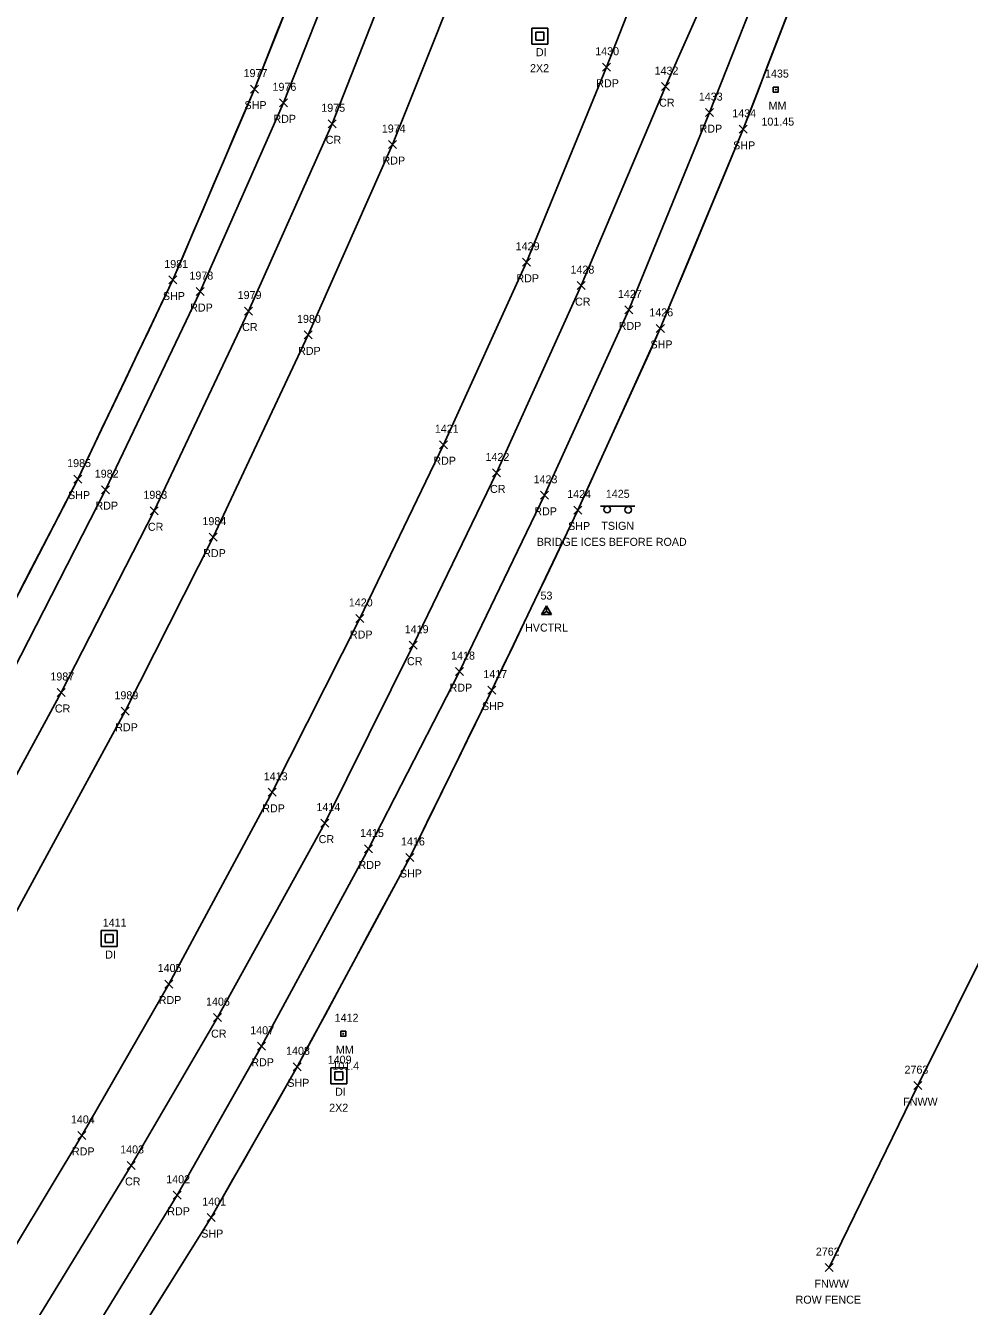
# Model space of a CAD drawing. Extents: x 1472022 to 1479249, y 777216 to 786527.
# Drawn here: x 1473340.4 to 1473576.1, y 778431.9 to 778752 of the extents above; entities that cross this region are included whole.
import ezdxf

# ---------------------------------------------------------------- set-up
doc = ezdxf.new("R2010")
doc.units = 0
for name, color, linetype in [('C_A', 7, 'Continuous'), ('C_I', 7, 'Continuous'), ('CPSM', 7, 'Continuous'), ('D_A', 7, 'Continuous'), ('D_C', 7, 'Continuous'), ('D_I', 7, 'Continuous'), ('DS', 7, 'Continuous'), ('L_A', 7, 'Continuous'), ('L_C', 7, 'Continuous'), ('L_I', 7, 'Continuous'), ('L_TIC', 7, 'Continuous'), ('LFNC', 7, 'Continuous'), ('LSOGP', 7, 'Continuous'), ('P_A', 7, 'Continuous'), ('P_I', 7, 'Continuous'), ('P_TIC', 7, 'Continuous'), ('PET', 7, 'Continuous'), ('PRC', 7, 'Continuous'), ('PSP', 7, 'Continuous'), ('S_A', 7, 'Continuous'), ('S_C', 7, 'Continuous'), ('S_I', 7, 'Continuous'), ('SRM', 7, 'Continuous'), ('SSGN', 7, 'Continuous')]:
    doc.layers.add(name, color=color, linetype=linetype)

msp = doc.modelspace()

# ---------------------------------------------------------------- linework, layer by layer
at = {"layer": 'CPSM'}
for p, q in [((1473469.19, 778604.84), (1473470.44, 778607.01)), ((1473469.19, 778604.84), (1473470.44, 778605.56)), ((1473469.19, 778604.84), (1473471.69, 778604.84)), ((1473471.69, 778604.84), (1473470.44, 778607.01)), ((1473470.44, 778605.56), (1473470.44, 778607.01)), ((1473470.44, 778605.56), (1473470.44, 778605.56)), ((1473470.44, 778605.56), (1473471.69, 778604.84))]:
    msp.add_line(p, q, dxfattribs=at)
at = {"layer": 'DS'}
for p, q in [((1473466.78, 778751.36), (1473470.78, 778751.36)), ((1473466.78, 778747.36), (1473466.78, 778751.36)), ((1473467.78, 778748.36), (1473467.78, 778750.36)), ((1473467.78, 778750.36), (1473469.78, 778750.36)), ((1473469.78, 778748.36), (1473467.78, 778748.36)), ((1473468.79, 778749.36), (1473468.79, 778749.36)), ((1473468.79, 778749.36), (1473468.79, 778749.36)), ((1473469.78, 778750.36), (1473469.78, 778748.36)), ((1473470.78, 778751.36), (1473470.78, 778747.36)), ((1473470.78, 778747.36), (1473466.78, 778747.36)), ((1473359.21, 778525.83), (1473363.21, 778525.83)), ((1473359.21, 778521.83), (1473359.21, 778525.83)), ((1473360.21, 778522.83), (1473360.21, 778524.83)), ((1473360.21, 778524.83), (1473362.21, 778524.83)), ((1473362.21, 778524.83), (1473362.21, 778522.83)), ((1473363.21, 778525.83), (1473363.21, 778521.83)), ((1473363.21, 778521.83), (1473359.21, 778521.83)), ((1473362.21, 778522.83), (1473360.21, 778522.83)), ((1473361.21, 778523.84), (1473361.21, 778523.84)), ((1473361.21, 778523.84), (1473361.21, 778523.84)), ((1473416.62, 778491.57), (1473420.62, 778491.57)), ((1473416.62, 778487.57), (1473416.62, 778491.57)), ((1473417.62, 778488.57), (1473417.62, 778490.57)), ((1473417.62, 778490.57), (1473419.62, 778490.57)), ((1473418.62, 778489.57), (1473418.62, 778489.57)), ((1473418.62, 778489.57), (1473418.62, 778489.57)), ((1473419.62, 778490.57), (1473419.62, 778488.57)), ((1473420.62, 778491.57), (1473420.62, 778487.57)), ((1473420.62, 778487.57), (1473416.62, 778487.57)), ((1473419.62, 778488.57), (1473417.62, 778488.57))]:
    msp.add_line(p, q, dxfattribs=at)
at = {"layer": 'L_TIC'}
for points in [[(1473562.21, 778486.09), (1473564.21, 778488.09)], [(1473564.21, 778486.09), (1473562.21, 778488.09)], [(1473540.06, 778440.61), (1473542.06, 778442.61)], [(1473542.06, 778440.61), (1473540.06, 778442.61)]]:
    msp.add_lwpolyline(points, dxfattribs=at)
at = {"layer": 'LFNC'}
msp.add_lwpolyline([(1473541.06, 778441.61), (1473563.21, 778487.09), (1473582.35, 778525.63), (1473607.06, 778564.79), (1473620.48, 778587.36), (1473636.9, 778615.99), (1473667.35, 778667.85), (1473688.74, 778703.58), (1473697.71, 778720.36), (1473722.81, 778762.74), (1473752.79, 778816.55), (1473766.47, 778860.32), (1473785.95, 778933.66), (1473793.25, 778964.66), (1473799.84, 778991.84), (1473803.88, 779010.25), (1473815.37, 779068.14), (1473825.67, 779115.79)], dxfattribs=at)
at = {"layer": 'LSOGP'}
for points in [[(1473405.86, 778757.09), (1473403.08, 778750.1), (1473400.3, 778743.12), (1473397.52, 778736.13), (1473394.97, 778730.17), (1473392.42, 778724.21), (1473389.87, 778718.24), (1473387.33, 778712.28), (1473384.78, 778706.32), (1473382.23, 778700.36), (1473379.69, 778694.39), (1473377.14, 778688.43), (1473374.18, 778682.21), (1473371.22, 778675.99), (1473368.26, 778669.77), (1473365.29, 778663.55), (1473362.33, 778657.33), (1473359.37, 778651.11), (1473356.41, 778644.89), (1473353.45, 778638.67), (1473350.53, 778633.06), (1473347.61, 778627.44), (1473344.69, 778621.83), (1473341.77, 778616.21), (1473338.85, 778610.6)], [(1473370.08, 778427.53), (1473373.41, 778432.85), (1473376.73, 778438.16), (1473380.06, 778443.48), (1473383.38, 778448.8), (1473386.71, 778454.12), (1473389.39, 778458.83), (1473392.08, 778463.54), (1473394.77, 778468.25), (1473397.46, 778472.96), (1473400.15, 778477.67), (1473402.84, 778482.38), (1473405.52, 778487.09), (1473408.21, 778491.8), (1473411.73, 778498.34), (1473415.24, 778504.88), (1473418.75, 778511.42), (1473422.27, 778517.96), (1473425.78, 778524.5), (1473429.3, 778531.03), (1473432.81, 778537.57), (1473436.32, 778544.11), (1473438.89, 778549.34), (1473441.45, 778554.57), (1473444.01, 778559.8), (1473446.58, 778565.02), (1473449.14, 778570.25), (1473451.7, 778575.48), (1473454.26, 778580.71), (1473456.83, 778585.94), (1473459.52, 778591.56), (1473462.21, 778597.19), (1473464.9, 778602.81), (1473467.59, 778608.44), (1473470.28, 778614.06), (1473472.97, 778619.69), (1473475.66, 778625.31), (1473478.34, 778630.94), (1473480.92, 778636.61), (1473483.49, 778642.29), (1473486.06, 778647.96), (1473488.63, 778653.63), (1473491.2, 778659.31), (1473493.77, 778664.98), (1473496.34, 778670.66), (1473498.91, 778676.33), (1473501.49, 778682.55), (1473504.08, 778688.77), (1473506.66, 778694.99), (1473509.24, 778701.21), (1473511.82, 778707.43), (1473514.41, 778713.64), (1473516.99, 778719.86), (1473519.57, 778726.08), (1473521.56, 778731.24), (1473523.56, 778736.4), (1473525.55, 778741.56), (1473527.54, 778746.72), (1473529.53, 778751.88), (1473531.53, 778757.04)]]:
    msp.add_lwpolyline(points, dxfattribs=at)
at = {"layer": 'P_TIC'}
for points in [[(1473484.43, 778740.59), (1473486.43, 778742.59)], [(1473486.43, 778740.59), (1473484.43, 778742.59)], [(1473396.52, 778735.13), (1473398.52, 778737.13)], [(1473398.52, 778735.13), (1473396.52, 778737.13)], [(1473499.17, 778735.74), (1473501.17, 778737.74)], [(1473501.17, 778735.74), (1473499.17, 778737.74)], [(1473403.79, 778731.7), (1473405.79, 778733.7)], [(1473405.79, 778731.7), (1473403.79, 778733.7)], [(1473510.23, 778729.25), (1473512.23, 778731.25)], [(1473512.23, 778729.25), (1473510.23, 778731.25)], [(1473415.92, 778726.46), (1473417.92, 778728.46)], [(1473417.92, 778726.46), (1473415.92, 778728.46)], [(1473518.57, 778725.08), (1473520.57, 778727.08)], [(1473520.57, 778725.08), (1473518.57, 778727.08)], [(1473431.04, 778721.28), (1473433.04, 778723.28)], [(1473433.04, 778721.28), (1473431.04, 778723.28)], [(1473464.48, 778691.86), (1473466.48, 778693.86)], [(1473466.48, 778691.86), (1473464.48, 778693.86)], [(1473376.14, 778687.43), (1473378.14, 778689.43)], [(1473378.14, 778687.43), (1473376.14, 778689.43)], [(1473478.17, 778686.02), (1473480.17, 778688.02)], [(1473480.17, 778686.02), (1473478.17, 778688.02)], [(1473382.99, 778684.53), (1473384.99, 778686.53)], [(1473384.99, 778684.53), (1473382.99, 778686.53)], [(1473395.04, 778679.67), (1473397.04, 778681.67)], [(1473397.04, 778679.67), (1473395.04, 778681.67)], [(1473490.01, 778679.96), (1473492.01, 778681.96)], [(1473492.01, 778679.96), (1473490.01, 778681.96)], [(1473409.95, 778673.71), (1473411.95, 778675.71)], [(1473411.95, 778673.71), (1473409.95, 778675.71)], [(1473497.91, 778675.33), (1473499.91, 778677.33)], [(1473499.91, 778675.33), (1473497.91, 778677.33)], [(1473443.72, 778646.26), (1473445.72, 778648.26)], [(1473445.72, 778646.26), (1473443.72, 778648.26)], [(1473352.45, 778637.67), (1473354.45, 778639.67)], [(1473354.45, 778637.67), (1473352.45, 778639.67)], [(1473456.95, 778639.21), (1473458.95, 778641.21)], [(1473458.95, 778639.21), (1473456.95, 778641.21)], [(1473359.34, 778635.02), (1473361.34, 778637.02)], [(1473361.34, 778635.02), (1473359.34, 778637.02)], [(1473468.94, 778633.62), (1473470.94, 778635.62)], [(1473470.94, 778633.62), (1473468.94, 778635.62)], [(1473371.49, 778629.75), (1473373.49, 778631.75)], [(1473373.49, 778629.75), (1473371.49, 778631.75)], [(1473477.34, 778629.94), (1473479.34, 778631.94)], [(1473479.34, 778629.94), (1473477.34, 778631.94)], [(1473386.24, 778623.16), (1473388.24, 778625.16)], [(1473388.24, 778623.16), (1473386.24, 778625.16)], [(1473422.89, 778602.83), (1473424.89, 778604.83)], [(1473424.89, 778602.83), (1473422.89, 778604.83)], [(1473436.21, 778596.16), (1473438.21, 778598.16)], [(1473438.21, 778596.16), (1473436.21, 778598.16)], [(1473447.78, 778589.55), (1473449.78, 778591.55)], [(1473449.78, 778589.55), (1473447.78, 778591.55)], [(1473348.26, 778584.34), (1473350.26, 778586.34)], [(1473350.26, 778584.34), (1473348.26, 778586.34)], [(1473455.83, 778584.94), (1473457.83, 778586.94)], [(1473457.83, 778584.94), (1473455.83, 778586.94)], [(1473364.27, 778579.65), (1473366.27, 778581.65)], [(1473366.27, 778579.65), (1473364.27, 778581.65)], [(1473400.99, 778559.39), (1473402.99, 778561.39)], [(1473402.99, 778559.39), (1473400.99, 778561.39)], [(1473414.13, 778551.7), (1473416.13, 778553.7)], [(1473416.13, 778551.7), (1473414.13, 778553.7)], [(1473425.04, 778545.24), (1473427.04, 778547.24)], [(1473427.04, 778545.24), (1473425.04, 778547.24)], [(1473435.32, 778543.11), (1473437.32, 778545.11)], [(1473437.32, 778543.11), (1473435.32, 778545.11)], [(1473375.14, 778511.49), (1473377.14, 778513.49)], [(1473377.14, 778511.49), (1473375.14, 778513.49)], [(1473387.27, 778503.09), (1473389.27, 778505.09)], [(1473389.27, 778503.09), (1473387.27, 778505.09)], [(1473398.26, 778495.93), (1473400.26, 778497.93)], [(1473400.26, 778495.93), (1473398.26, 778497.93)], [(1473407.21, 778490.8), (1473409.21, 778492.8)], [(1473409.21, 778490.8), (1473407.21, 778492.8)], [(1473353.46, 778473.65), (1473355.46, 778475.65)], [(1473355.46, 778473.65), (1473353.46, 778475.65)], [(1473365.77, 778466.15), (1473367.77, 778468.15)], [(1473367.77, 778466.15), (1473365.77, 778468.15)], [(1473377.27, 778458.7), (1473379.27, 778460.7)], [(1473379.27, 778458.7), (1473377.27, 778460.7)], [(1473385.71, 778453.12), (1473387.71, 778455.12)], [(1473387.71, 778453.12), (1473385.71, 778455.12)]]:
    msp.add_lwpolyline(points, dxfattribs=at)
at = {"layer": 'PET'}
for points in [[(1473559.55, 779345.54), (1473562.13, 779344.85), (1473559.08, 779325.48), (1473547.78, 779268.19), (1473538.56, 779219.47), (1473529.75, 779172.07), (1473520.23, 779121.16), (1473510.25, 779071.91), (1473501.42, 779032.79), (1473487.97, 778980.7), (1473476.59, 778937.83), (1473460.83, 778885.95), (1473443.7, 778834.83), (1473427.04, 778789.1), (1473404.79, 778732.7), (1473383.99, 778685.53), (1473360.34, 778636.02), (1473337.25, 778590.82), (1473309.69, 778539.48), (1473284.14, 778496.13), (1473255.52, 778449.63), (1473221.14, 778399.57)], [(1473562.13, 779344.85), (1473573.79, 779342.6), (1473588.74, 779339.91), (1473585.78, 779323.26), (1473585.84, 779321.4), (1473576.73, 779269.38), (1473567.96, 779217.59), (1473558.64, 779166.28), (1473549.3, 779116.91), (1473539.05, 779065.97), (1473530.44, 779026.51), (1473516.8, 778971.79), (1473504.7, 778929.77), (1473489.22, 778877.79), (1473471.58, 778825.33), (1473455.05, 778780.13), (1473432.04, 778722.28), (1473410.95, 778674.71), (1473387.24, 778624.16), (1473365.27, 778580.65), (1473335.21, 778525.25), (1473309.35, 778481.56), (1473280.39, 778434.36), (1473245.89, 778383.45)], [(1473301.45, 778389.87), (1473329.64, 778433.49), (1473354.46, 778474.65), (1473376.14, 778512.49), (1473401.99, 778560.39), (1473423.89, 778603.83), (1473444.72, 778647.26), (1473465.48, 778692.86), (1473485.43, 778741.59), (1473500.45, 778779.97), (1473517.46, 778826.05), (1473530.33, 778868.32), (1473543.81, 778911.93), (1473556.66, 778958.65), (1473567.98, 779002.48), (1473580.14, 779054.81), (1473589.43, 779101.31), (1473598.46, 779148.03), (1473608.13, 779200.81), (1473618, 779253.28), (1473624.21, 779286.68), (1473629.11, 779313.19), (1473632.64, 779331.64)], [(1473351.95, 778416.72), (1473378.27, 778459.7), (1473399.26, 778496.93), (1473426.04, 778546.24), (1473448.78, 778590.55), (1473469.94, 778634.62), (1473491.01, 778680.96), (1473511.23, 778730.25), (1473526.94, 778770.17), (1473542.8, 778815.57), (1473557.74, 778859.7), (1473571.44, 778904.64), (1473584.34, 778950.97), (1473595.35, 778994.87), (1473607.13, 779045.13), (1473617.39, 779095.53), (1473626.97, 779145.31), (1473636.44, 779196.8), (1473646.17, 779249.15), (1473652.07, 779281.25), (1473656.8, 779307.9), (1473660.32, 779326.69), (1473648.23, 779328.95), (1473632.64, 779331.64)]]:
    msp.add_lwpolyline(points, dxfattribs=at)
at = {"layer": 'PRC'}
for points in [[(1473573.79, 779342.6), (1473570.41, 779324.08), (1473560.67, 779266.03), (1473551.92, 779218.05), (1473542.92, 779169.19), (1473533.33, 779119.74), (1473523.22, 779068.95), (1473514.33, 779029.92), (1473501.09, 778976.92), (1473489.49, 778934.86), (1473473.76, 778882.81), (1473456.11, 778830.27), (1473439.73, 778785.61), (1473416.92, 778727.46), (1473396.04, 778680.67), (1473372.49, 778630.75), (1473349.26, 778585.34), (1473321.1, 778533.63), (1473295.37, 778489.48), (1473266.55, 778442.63), (1473232.46, 778392.44)], [(1473340.44, 778424.05), (1473366.77, 778467.15), (1473388.27, 778504.09), (1473415.13, 778552.7), (1473437.21, 778597.16), (1473457.95, 778640.21), (1473479.17, 778687.02), (1473500.17, 778736.74), (1473516.94, 778774.63), (1473530.88, 778819.91), (1473544.58, 778863.11), (1473558.69, 778908.68), (1473571.41, 778953.91), (1473582.65, 778997.42), (1473594.11, 779047.2), (1473604.41, 779097.99), (1473613.95, 779144.11), (1473624.22, 779197.73), (1473633.15, 779249.53), (1473640.4, 779286.65), (1473645.03, 779310.08), (1473648.23, 779328.95)]]:
    msp.add_lwpolyline(points, dxfattribs=at)
at = {"layer": 'PSP'}
for points in [[(1473559.55, 779345.54), (1473556.55, 779328.39), (1473555.66, 779326.52), (1473543.65, 779268.7), (1473533.24, 779220.88), (1473523.59, 779172.64), (1473513.3, 779122.79), (1473502.95, 779073.62), (1473494.24, 779034.96), (1473482.21, 778985.43), (1473469.56, 778939.68), (1473453.46, 778887.37), (1473437.09, 778838.65), (1473419.76, 778792.02), (1473397.52, 778736.13), (1473377.14, 778688.43), (1473353.45, 778638.67), (1473330.09, 778593.76), (1473303, 778543.94), (1473277.25, 778499.77), (1473248.4, 778453.47), (1473214.72, 778403.13)], [(1473360.11, 778411.57), (1473386.71, 778454.12), (1473408.21, 778491.8), (1473436.32, 778544.11), (1473456.83, 778585.94), (1473478.34, 778630.94), (1473498.91, 778676.33), (1473519.57, 778726.08), (1473535.51, 778767.36), (1473551.79, 778812.35), (1473566.71, 778857.26), (1473580.68, 778902.68), (1473593.4, 778949.04), (1473604.43, 778993.44), (1473615.75, 779042.5), (1473626.64, 779093.98), (1473636.29, 779143.66), (1473644.06, 779195.83), (1473651.7, 779249.18), (1473655.52, 779279.56), (1473658.83, 779307.84), (1473662.07, 779326.37), (1473660.32, 779326.69)]]:
    msp.add_lwpolyline(points, dxfattribs=at)
at = {"layer": 'SRM'}
for points in [[(1473527.13, 778736.64), (1473528.38, 778736.64), (1473528.38, 778735.39), (1473527.13, 778735.39)], [(1473419.07, 778500.68), (1473420.32, 778500.68), (1473420.32, 778499.43), (1473419.07, 778499.43)]]:
    msp.add_lwpolyline(points, close=True, dxfattribs=at)
for centre in [(1473527.75, 778736.01), (1473419.69, 778500.05)]:
    msp.add_circle(centre, 0.0833, dxfattribs=at)
at = {"layer": 'SSGN'}
for p, q in [((1473483.98, 778631.91), (1473492.58, 778631.91)), ((1473488, 778631.01), (1473488, 778631.01))]:
    msp.add_line(p, q, dxfattribs=at)
for centre in [(1473485.64, 778631.08), (1473490.86, 778631.01)]:
    msp.add_circle(centre, 0.833, dxfattribs=at)

# ---------------------------------------------------------------- texts
at = {"layer": 'C_A'}
msp.add_text('HVCTRL', height=2, dxfattribs=at).set_placement((1473465.13, 778600.56))
at = {"layer": 'C_I'}
msp.add_text('53', height=2, dxfattribs=at).set_placement((1473468.98, 778608.56))
at = {"layer": 'D_A'}
for p in [(1473467.84, 778744.36), (1473360.27, 778518.84), (1473417.68, 778484.57)]:
    msp.add_text('DI', height=2, dxfattribs=at).set_placement(p)
at = {"layer": 'D_C'}
for p in [(1473466.36, 778740.36), (1473416.2, 778480.57)]:
    msp.add_text('2X2', height=2, dxfattribs=at).set_placement(p)
at = {"layer": 'D_I'}
for s, p in [('1411', (1473359.65, 778526.84)), ('1409', (1473415.84, 778492.57))]:
    msp.add_text(s, height=2, dxfattribs=at).set_placement(p)
at = {"layer": 'L_A'}
for p in [(1473559.56, 778482.09), (1473537.4, 778436.61)]:
    msp.add_text('FNWW', height=2, dxfattribs=at).set_placement(p)
at = {"layer": 'L_C'}
msp.add_text('ROW FENCE', height=2, dxfattribs=at).set_placement((1473532.69, 778432.61))
at = {"layer": 'L_I'}
for s, p in [('2763', (1473559.9, 778490.09)), ('2762', (1473537.75, 778444.61))]:
    msp.add_text(s, height=2, dxfattribs=at).set_placement(p)
at = {"layer": 'P_A'}
for s, p in [('RDP', (1473482.91, 778736.59)), ('SHP', (1473395.05, 778731.13)), ('CR', (1473498.61, 778731.74)), ('RDP', (1473402.28, 778727.7)), ('RDP', (1473508.71, 778725.25)), ('CR', (1473415.35, 778722.46)), ('SHP', (1473517.1, 778721.08)), ('RDP', (1473429.53, 778717.28)), ('RDP', (1473462.97, 778687.86)), ('SHP', (1473374.67, 778683.43)), ('RDP', (1473381.48, 778680.53)), ('CR', (1473477.6, 778682.02)), ('RDP', (1473488.5, 778675.96)), ('CR', (1473394.47, 778675.67)), ('RDP', (1473408.44, 778669.71)), ('SHP', (1473496.45, 778671.33)), ('RDP', (1473442.21, 778642.26)), ('CR', (1473456.38, 778635.21)), ('SHP', (1473350.99, 778633.67)), ('RDP', (1473357.83, 778631.02)), ('RDP', (1473467.43, 778629.62)), ('CR', (1473370.92, 778625.75)), ('SHP', (1473475.88, 778625.94)), ('RDP', (1473384.73, 778619.16)), ('RDP', (1473421.38, 778598.83)), ('CR', (1473435.64, 778592.16)), ('RDP', (1473446.27, 778585.55)), ('CR', (1473347.69, 778580.34)), ('SHP', (1473454.36, 778580.94)), ('RDP', (1473362.76, 778575.65)), ('RDP', (1473399.48, 778555.39)), ('CR', (1473413.57, 778547.7)), ('RDP', (1473423.53, 778541.24)), ('SHP', (1473433.86, 778539.11)), ('RDP', (1473373.63, 778507.49)), ('CR', (1473386.7, 778499.09)), ('RDP', (1473396.75, 778491.93)), ('SHP', (1473405.75, 778486.8)), ('RDP', (1473351.95, 778469.65)), ('CR', (1473365.21, 778462.15)), ('RDP', (1473375.76, 778454.7)), ('SHP', (1473384.24, 778449.12))]:
    msp.add_text(s, height=2, dxfattribs=at).set_placement(p)
at = {"layer": 'P_I'}
for s, p in [('1430', (1473482.65, 778744.59)), ('1977', (1473394.82, 778739.13)), ('1432', (1473497.48, 778739.74)), ('1976', (1473402.05, 778735.7)), ('1975', (1473414.23, 778730.46)), ('1433', (1473508.53, 778733.25)), ('1434', (1473516.88, 778729.08)), ('1974', (1473429.35, 778725.28)), ('1429', (1473462.78, 778695.86)), ('1981', (1473375.01, 778691.43)), ('1428', (1473476.48, 778690.02)), ('1978', (1473381.3, 778688.53)), ('1979', (1473393.34, 778683.67)), ('1427', (1473488.32, 778683.96)), ('1426', (1473496.16, 778679.33)), ('1980', (1473408.17, 778677.71)), ('1421', (1473442.59, 778650.26)), ('1985', (1473350.76, 778641.67)), ('1422', (1473455.25, 778643.21)), ('1982', (1473357.65, 778639.02)), ('1423', (1473467.25, 778637.62)), ('1983', (1473369.8, 778633.75)), ('1424', (1473475.65, 778633.94)), ('1984', (1473384.55, 778627.16)), ('1420', (1473421.11, 778606.83)), ('1419', (1473435.07, 778600.16)), ('1418', (1473446.66, 778593.55)), ('1987', (1473346.57, 778588.34)), ('1417', (1473454.7, 778588.94)), ('1989', (1473362.57, 778583.65)), ('1413', (1473399.86, 778563.39)), ('1414', (1473413.01, 778555.7)), ('1415', (1473423.92, 778549.24)), ('1416', (1473434.14, 778547.11)), ('1405', (1473373.37, 778515.49)), ('1406', (1473385.44, 778507.09)), ('1407', (1473396.49, 778499.93)), ('1408', (1473405.44, 778494.8)), ('1404', (1473351.69, 778477.65)), ('1403', (1473364, 778470.15)), ('1402', (1473375.5, 778462.7)), ('1401', (1473384.5, 778457.12))]:
    msp.add_text(s, height=2, dxfattribs=at).set_placement(p)
at = {"layer": 'S_A'}
for s, p in [('MM', (1473525.94, 778731.01)), ('TSIGN', (1473484.18, 778625.99)), ('MM', (1473417.88, 778495.05))]:
    msp.add_text(s, height=2, dxfattribs=at).set_placement(p)
at = {"layer": 'S_C'}
for s, p in [('101.45', (1473524.16, 778727.01)), ('BRIDGE ICES BEFORE ROAD', (1473468.05, 778621.99)), ('101.4', (1473417, 778491.05))]:
    msp.add_text(s, height=2, dxfattribs=at).set_placement(p)
at = {"layer": 'S_I'}
for s, p in [('1435', (1473525.06, 778739.01)), ('1425', (1473485.3, 778633.99)), ('1412', (1473417.57, 778503.05))]:
    msp.add_text(s, height=2, dxfattribs=at).set_placement(p)

doc.saveas('drawing.dxf')
